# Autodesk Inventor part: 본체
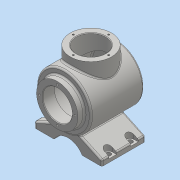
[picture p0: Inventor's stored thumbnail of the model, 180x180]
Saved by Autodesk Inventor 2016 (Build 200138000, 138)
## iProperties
Created: 2021-04
Part Number: 본체
Material: Generic
Document SubType Name: Modeling
Designer: User
Density: 1 g/cm^3
Appearance: Default
Author: User
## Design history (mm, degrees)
sketch "스케치1"
  geometry: L1 (0, 0)-(-120, 0); L2 (0, 0)-(0, 50); L3 (0, 50)-(-108, 50); L4 (-108, 50)-(-108, 38); L5 (-108, 38)-(-120, 38); L6 (-120, 38)-(-120, 0)
  constraints: 13 end point, 4 perpendicular, 1 horizontal, 1 vertical
  dimensions: "d2" = 12 distance of L4.end L5.end; "d3" = 100 diameter of L3 L1; "d4" = 76 diameter of L5 L1; "d6" = 108 distance of L2.end L3.end
revolve "회전1" sketch "스케치1" stored, may be unused: angle "d7" = 90 deg
sketch "스케치2"
  geometry: L1 (-108, 50)-(0, 50) reference; L2 (0, -50)-(0, 50) reference; L3 (-108, -50)-(0, -50) reference; L4 (-11.664, 50)-(0, 50); L5 (0, 50)-(0, 0); L6 (0, 0)-(-37.024, 0); A1 r 113 centre (-113, 0) between (0, 0) and (-11.664, 50)
  constraints: 6 end point, 4 point on circle, 2 horizontal, 2 point on line, 1 centre point
  dimensions: "d8" = 226 diameter of A1
revolve "회전2" sketch "스케치2" stored, may be unused: angle "d9" = 90 deg
sketch "스케치3"
  geometry: L1 (-120, -38)-(-120, 38) reference; L2 (-120, 0)-(0, 0); L3 (-120, 0)-(-120, 27); L4 (-120, 27)-(-98, 27); L5 (-98, 27)-(-98, 40); L6 (-98, 40)-(-18.084, 40); A1 r 113 centre (-113, 0) between (-11.664, -50) and (-11.664, 50) reference; A2 r 103 centre (-113, 0) between (-10, 0) and (-18.084, 40)
  constraints: 10 end point, 2 horizontal, 2 perpendicular, 2 point on circle, 2 point on line, 1 centre point, 1 midpoint
  dimensions: "d10" = 10 radial gap between concentric circles of A1 A2; "d11" = 54 diameter of L4 L2; "d12" = 22 distance of L3.end L4.end; "d13" = 80 diameter of L6 L2
revolve "회전3" sketch "스케치3" stored, may be unused: angle "d14" = 90 deg
node "작업 평면1"
sketch "스케치4"
  geometry: L1 (-18.193, -46.573)-(-62, -67); L2 (-62, -67)-(-62, -77); L3 (62, -77)-(62, -67); L4 (62, -67)-(18.193, -46.573); L5 (-62, -77)-(-25.981, -77); L6 (25.981, -77)-(62, -77); A1 r 50 centre (0, 0) between (-18.193, -46.573) and (18.193, -46.573) reference; A2 r 30 centre (0, -92) between (25.981, -77) and (-25.981, -77); 2 further points
  constraints: 12 end point, 4 perpendicular, 4 point on circle, 2 vertical alignment, 1 centre point, 1 vertical
  dimensions: "d17" = 60 diameter of A2; "d19" = 124 distance between parallel lines of L3 L2; "d20" = 65 deg angle of L2 L1; "d21" = 65 deg angle of L3 L4; "d22" = 10 distance of L1.end L2.end; "d23" = 10 distance of L3.start L3.end; "d90" = 77 distance from line of L6 point (0, 0); "d91" = 77 distance from line of L5 point (0, 0) (= d90); "d93" = 15 distance centre to line of A2 L6
extrude "돌출1" join sketch "스케치4" distance "d24" = 80; taper "d25" = 0 deg
sketch "스케치5"
  geometry: L1 (-87.981, 0)-(-87.981, 80) reference; L2 (-51.962, 0)-(-87.981, 0) reference; 5 further points
  constraints: 2 horizontal alignment, 2 vertical alignment
  dimensions: "d26" = 108 distance of point (-79.981, 20) point (28.019, 20); "d27" = 8 distance from line of point (-79.981, 20) L1; "d28" = 20 distance from line of L2 point (-79.981, 20); "d29" = 40 distance of point (-79.981, 60) point (-79.981, 20)
hole "구멍1" sketch "스케치5" at (28.019, 20), (-79.981, 20), (-79.981, 60), (28.019, 60) diameter "d30" = 9; stored, may be unused: countersink angle "d34" = 90 deg, drill point angle "d36" = 118 deg; dims "d31" = 6, "d32" = 4, "d33" = 2, "d35" = 20
node "작업 평면2"
sketch "스케치6"
  geometry: L1 (-40.161, 67)-(-40.161, 53); L2 (-28.019, 67)-(-40.161, 67); L3 (-28.019, 53)-(-40.161, 53); L4 (-36.019, 0)-(-36.019, 80) reference; L5 (-36.019, 40)-(87.981, 40); L6 (87.981, 0)-(87.981, 80) reference; L7 (-28.019, 27)-(-40.161, 27); L8 (-28.019, 13)-(-40.161, 13); L9 (-40.161, 13)-(-40.161, 27); C1 r 4.5 at (-28.019, 60) reference; A1 r 7 centre (-28.019, 60) between (-28.019, 53) and (-28.019, 67); A2 r 7 centre (-28.019, 20) between (-28.019, 13) and (-28.019, 27); 2 further points
  constraints: 14 end point, 5 symmetric about line, 4 point on circle, 3 midpoint, 2 centre point, 1 coincident, 1 horizontal alignment, 1 parallel, 1 tangent, 1 vertical, 1 other
  dimensions: "d38" = 14 distance of L1.start L1.end; "d39" = 14 diameter of A1
extrude "돌출2" cut sketch "스케치6" distance "d40" = 20; taper "d41" = 0 deg
node "작업 평면3"
sketch "스케치7"
  geometry: L1 (-112, -8)-(-112, 88.336) reference; L2 (-12, -8)-(-112, -8) reference; L3 (-24, -20)-(-100, -20) reference; C1 r 38 at (-62, 42); 1 further point
  constraints: 1 centre point, 1 vertical alignment
  dimensions: "d43" = 76 diameter of C1; "d92" = 62 distance from line of L3 C1.centre
extrude "돌출3" join sketch "스케치7" stored distance "d44" = 80; taper "d45" = 0 deg
hole "구멍2" diameter "d48" = 54; stored, may be unused: countersink angle "d52" = 90 deg, drill point angle "d54" = 118 deg; dims "d49" = 6, "d50" = 4, "d51" = 2, "d53" = 8, "d55" = 10, "d56" = 10
sketch "스케치8"
  geometry: 2 further points
  constraints: 1 vertical alignment
  dimensions: "d57" = 32.5 distance of point (0, 0) point (0, 32.5)
hole "구멍3" sketch "스케치8" at (0, 32.5) diameter "d58" = 3.242; stored, may be unused: countersink angle "d62" = 90 deg, drill point angle "d64" = 118 deg; dims "d59" = 8, "d60" = 4, "d61" = 2, "d63" = 10
sketch "스케치9"
  geometry: C1 r 27 at (0, 0) reference; 2 further points
  constraints: 1 vertical alignment
  dimensions: "d68" = 32.5 distance of point (0, -32.5) C1.centre
hole "구멍4" sketch "스케치9" at (0, -32.5) diameter "d69" = 3.242; stored, may be unused: countersink angle "d73" = 90 deg, drill point angle "d75" = 118 deg; dims "d70" = 8, "d71" = 4, "d72" = 2, "d74" = 10
chamfer "모따기1" distance "d79" = 1; stored, may be unused: second distance "d80" = 2, angle "d81" = 45 deg
fillet "모깎기1" dims "d82" = 3
fillet "모깎기2" dims "d83" = 3
fillet "모깎기3" dims "d84" = 3
node "작업 평면4"
node "작업 평면5"
sketch "스케치11"
  geometry: 2 further points
  constraints: 1 coincident, 1 other
feature "엠보싱1" sketch "스케치11" dims "d2" = 12, "d3" = 100, "d4" = 76, "d6" = 108, "d86" = 0.5, "d87" = 0
fillet "모깎기4" dims "d88" = 3
node "솔리드1"
mirror "대칭1"
pattern_circular "원형 패턴1" dims angle "d66" = 360 deg
pattern_circular "원형 패턴2" dims angle "d77" = 360 deg
other parameters: "d18" = 15, "d37" = -6, "d42" = -142, "d85" = 0.5
